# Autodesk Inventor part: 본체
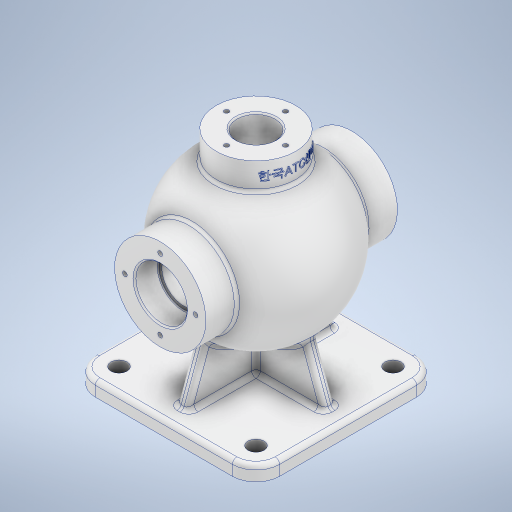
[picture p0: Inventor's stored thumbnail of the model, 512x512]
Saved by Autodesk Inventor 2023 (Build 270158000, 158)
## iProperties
Created: 2023-07
Part Number: 본체
Material: 알루미늄 6061
Document SubType Name: Modeling
Designer: Owner
Density: 2.7 g/cm^3
Appearance: 알루미늄 - 평지
Mass: 1526.72 g
Surface Area: 1173.82 cm^2
Volume: 565.453 cm^3
Author: Owner
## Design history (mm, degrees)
sketch "스케치2"
  geometry: L1 (62.5, -62.5)-(-62.5, -62.5); L2 (-62.5, -62.5)-(-62.5, 62.5); L3 (-62.5, 62.5)-(62.5, 62.5); L4 (62.5, 62.5)-(62.5, -62.5); L5 (62.5, -62.5)-(-62.5, 62.5); L6 (-62.5, -62.5)-(62.5, 62.5); 1 further point
  constraints: 12 end point, 2 midpoint, 2 parallel, 1 horizontal, 1 perpendicular
  dimensions: "d0" = 125 distance of L1.start L1.end; "d1" = 125 distance of L1.end L2.end
extrude "돌출1" new body sketch "스케치2" distance "d2" = 10; taper "d3" = 0 deg
fillet "모깎기1" dims "d5" = 16
sketch "스케치4"
  geometry: C1 r 5.5 at (-46.5, 46.5); C2 r 5.5 at (46.5, 46.5); C3 r 5.5 at (46.5, -46.5); C4 r 5.5 at (-46.5, -46.5); A1 r 16 centre (-46.5, 46.5) between (-46.5, 62.5) and (-62.5, 46.5) reference; A2 r 16 centre (-46.5, -46.5) between (-62.5, -46.5) and (-46.5, -62.5) reference; A3 r 16 centre (46.5, -46.5) between (46.5, -62.5) and (62.5, -46.5) reference; A4 r 16 centre (46.5, 46.5) between (62.5, 46.5) and (46.5, 62.5) reference; 1 further point
  constraints: 4 centre point, 4 coincident
  dimensions: "d6" = 11 diameter of C1; "d7" = 11 diameter of C2; "d8" = 11 diameter of C3; "d9" = 11 diameter of C4
extrude "돌출2" cut sketch "스케치4" extent not by distance; stored distance "d10" = 0; taper "d11" = 0 deg
fillet "모깎기2" dims "d12" = 3
sketch "스케치5"
  geometry: L1 (85, 65)-(85, -65); L2 (85, -65)-(54, -65); L3 (0, 46.5)-(0, -46.5) reference; L4 (85, 65)-(54, 65); L5 (54, 65)-(54, 44.215); L6 (54, -65)-(54, -44.215); A1 r 54 centre (85, 0) between (54, 44.215) and (54, -44.215); 3 further points
  constraints: 10 end point, 2 midpoint, 2 perpendicular, 2 point on circle, 2 vertical, 1 centre point, 1 coincident, 1 collinear, 1 horizontal, 1 horizontal alignment
  dimensions: "d13" = 130 distance of L1.start L1.end; "d14" = 85 distance from line of L3 point (85, 0); "d15" = 31 distance of L1.end L2.end; "d16" = 54 radius of A1
revolve "회전1" sketch "스케치5" stored, may be unused: angle "d17" = 90 deg
sketch "스케치6"
  geometry: L1 (7, -62.5)-(0, -62.5) reference; L2 (0, -62.5)-(0, 62.5) reference; L3 (0, 62.5)-(7, 62.5) reference; L4 (10, 59.5)-(10, -59.5) reference; L5 (54, 65)-(116, 65) reference; L6 (116, 65)-(116, 44.215) reference; L7 (116, -44.215)-(116, -65) reference; L8 (116, -65)-(54, -65) reference; L9 (54, -65)-(54, -44.215) reference; L10 (54, 44.215)-(54, 65) reference; L11 (10, 46.5)-(10, -46.5) reference; L12 (10, 50.5)-(83.668, 23.687); L13 (83.668, 23.687)-(83.668, -23.687); L14 (83.668, -23.687)-(10, -50.5); A1 r 3 centre (7, -59.5) between (7, -62.5) and (10, -59.5) reference; A2 r 3 centre (7, 59.5) between (10, 59.5) and (7, 62.5) reference; A3 r 54 centre (85, 0) between (116, -44.215) and (116, 44.215) reference; A4 r 54 centre (85, 0) between (54, 44.215) and (54, -44.215) reference; 7 further points
  constraints: 6 end point, 2 midpoint, 2 point on line, 1 parallel
  dimensions: "d18" = 12 vertical distance of L12.start point (3.5, 62.5); "d19" = 20 deg angle of L12 L3; "d20" = 12 vertical distance of point (3.5, -62.5) L14.end; "d21" = 20 deg angle of L1 L14; "d22" = 83.66811 distance between parallel lines of L2 L13
extrude "돌출3" join sketch "스케치6" stored distance "d23" = 8; taper "d24" = 0 deg
sketch "스케치7"
  geometry: L1 (62.5, 7)-(62.5, 0) reference; L2 (62.5, 0)-(-62.5, 0) reference; L3 (-62.5, 0)-(-62.5, 7) reference; L4 (-59.5, 10)-(-4, 10) reference; L5 (-4, 10)-(-4, 31.148) reference; L6 (4, 31.148)-(4, 10) reference; L7 (4, 10)-(59.5, 10) reference; L8 (-46.5, 10)-(46.5, 10) reference; L9 (50.5, 10)-(41.398, 35.008); A1 r 3 centre (59.5, 7) between (62.5, 7) and (59.5, 10) reference; A2 r 3 centre (-59.5, 7) between (-59.5, 10) and (-62.5, 7) reference; A3 r 54 centre (0, 85) between (4, 31.148) and (-4, 31.148) reference; 2 further points
  constraints: 2 end point, 1 midpoint, 1 point on line
  dimensions: "d25" = 12 horizontal distance of point (62.5, 3.5) L9.start; "d26" = 20 deg angle of L1 L9
feature "리브1" sketch "스케치7" dims "d27" = 1, "d28" = 8, "d29" = 0, "d30" = 0, "d31" = 1, "d32" = 1
sketch "스케치8"
  geometry: C1 r 31 at (0, 0) reference; C2 r 15 at (0, 0); 1 further point
  constraints: 1 centre point, 1 coincident
  dimensions: "d33" = 30 diameter of C2
fillet "모깎기3" dims "d48" = 3
fillet "모깎기4" dims "d49" = 3
node "작업 평면1"
sketch "스케치11"
  geometry: C1 r 27 at (0, 0); 1 further point
  constraints: 1 centre point, 1 coincident
  dimensions: "d51" = 54 diameter of C1
extrude "돌출5" join sketch "스케치11" stored distance "d52" = 10; taper "d53" = 0 deg
sketch "스케치12"
  geometry: C1 r 27 at (0, 0) reference; C2 r 13 at (0, 0)
  constraints: 1 centre point, 1 coincident
  dimensions: "d54" = 26 diameter of C2
sketch "스케치13" dims "d57" = 40
  geometry: C1 r 13 at (0, 0) reference; C2 r 27 at (0, 0) reference; 2 further points
  constraints: 2 vertical alignment, 1 coincident, 2 other
hole "구멍2" sketch "스케치13" at (0, 20) diameter "d58" = 3.242; stored, may be unused: countersink angle "d62" = 90 deg, drill point angle "d64" = 118 deg; dims "d59" = 9, "d60" = 4, "d61" = 2, "d63" = 11
fillet "모깎기5" dims "d68" = 3
fillet "모깎기6" dims "d69" = 3
sketch "스케치14"
  geometry: L1 (0, 0)-(140.594, 0); C1 r 44 at (85, 0); 3 further points
  constraints: 2 end point, 1 centre point, 1 coincident, 1 horizontal, 1 horizontal alignment
  dimensions: "d70" = 88 diameter of C1; "d72" = 85 distance of point (0, 0) C1.centre
revolve "회전2" stored, may be unused: angle "d76" = 90 deg
extrude "돌출7" cut sketch "스케치8" extent not by distance; stored distance "d77" = 0; taper "d78" = 0 deg
extrude "돌출8" cut sketch "스케치12" stored distance "d79" = 10; taper "d80" = 0 deg
sketch "스케치16"
  geometry: C1 r 31 at (0, 0) reference; C2 r 17.5 at (0, 0); 1 further point
  constraints: 1 centre point, 1 coincident
  dimensions: "d91" = 35 diameter of C2
extrude "돌출9" cut sketch "스케치16" distance "d92" = 16; taper "d93" = 0 deg
fillet "모깎기8" dims "d94" = 0.6
fillet "모깎기9" dims "d95" = 0.6
chamfer "모따기2" distance "d96" = 1; stored, may be unused: second distance "d97" = 2, angle "d98" = 45 deg
node "작업 평면2"
sketch "스케치17"
  geometry: L1 (150, -27)-(150, 27) reference; L2 (0, 46.5)-(0, -46.5) reference; 3 further points
  constraints: 1 horizontal alignment, 1 midpoint, 1 other
  dimensions: "d100" = 9 distance from line of L1 point (141, 0)
feature "엠보싱1" sketch "스케치17" dims "d101" = 0.5, "d102" = 0
fillet "모깎기10" dims "d103" = 3
sketch "스케치18" dims "d104" = 48
  geometry: C1 r 31 at (0, 0) reference; C2 r 18.5 at (0, 0) reference; 3 further points
  constraints: 2 vertical alignment, 1 coincident, 2 other
hole "구멍3" sketch "스케치18" at (0, 24) diameter "d105" = 3.242; stored, may be unused: countersink angle "d109" = 90 deg, drill point angle "d111" = 118 deg; dims "d106" = 12, "d107" = 4, "d108" = 2, "d110" = 15
feature "ɕ耀ɗ耀ə耀ɛ耀ɝ耀ɟ耀ɡ耀ɣ耀" dims "d0" = 125, "d1" = 125, "d2" = 10, "d3" = 0, "d5" = 16, "d6" = 11, "d7" = 11, "d8" = 11, "d9" = 11, "d10" = 0, "d11" = 0, "d12" = 3, "d13" = 130, "d14" = 85, "d15" = 31, "d16" = 54, "d17" = 90 deg, "d18" = 12, "d19" = 20 deg, "d20" = 12, "d21" = 20 deg, "d22" = 83.66811, "d23" = 8, "d24" = 0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
node "솔리드1"
mirror "미러1"
pattern_circular "원형 패턴3" dims angle "d74" = 360 deg
mirror "미러3"
pattern_circular "원형 패턴6" dims angle "d113" = 360 deg
mirror "미러4"
node "절단 모서리 투영1"
node "절단 모서리 투영2"
feature "A9D066F2-1C7D-4E18-AEED-F7BC21143FA4" dims "d58" = 3.242, "d59" = 9, "d60" = 4, "d61" = 2, "d62" = 90 deg, "d63" = 11, "d64" = 118 deg
